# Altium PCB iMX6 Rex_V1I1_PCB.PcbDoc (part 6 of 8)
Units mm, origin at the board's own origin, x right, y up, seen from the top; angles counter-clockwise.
Board outline 70 x 40 mm, 12 copper layers (L1, L2, L3, L4, L5 (PWR), L6 (PWR), L7 (PWR), L8 (PWR), L9, L10, L11, L12), stack 1.566 mm thick; 473 components, 409 nets, 2294 pads, 1880 vias.
Unrouted connection lines stored in the file: 7.
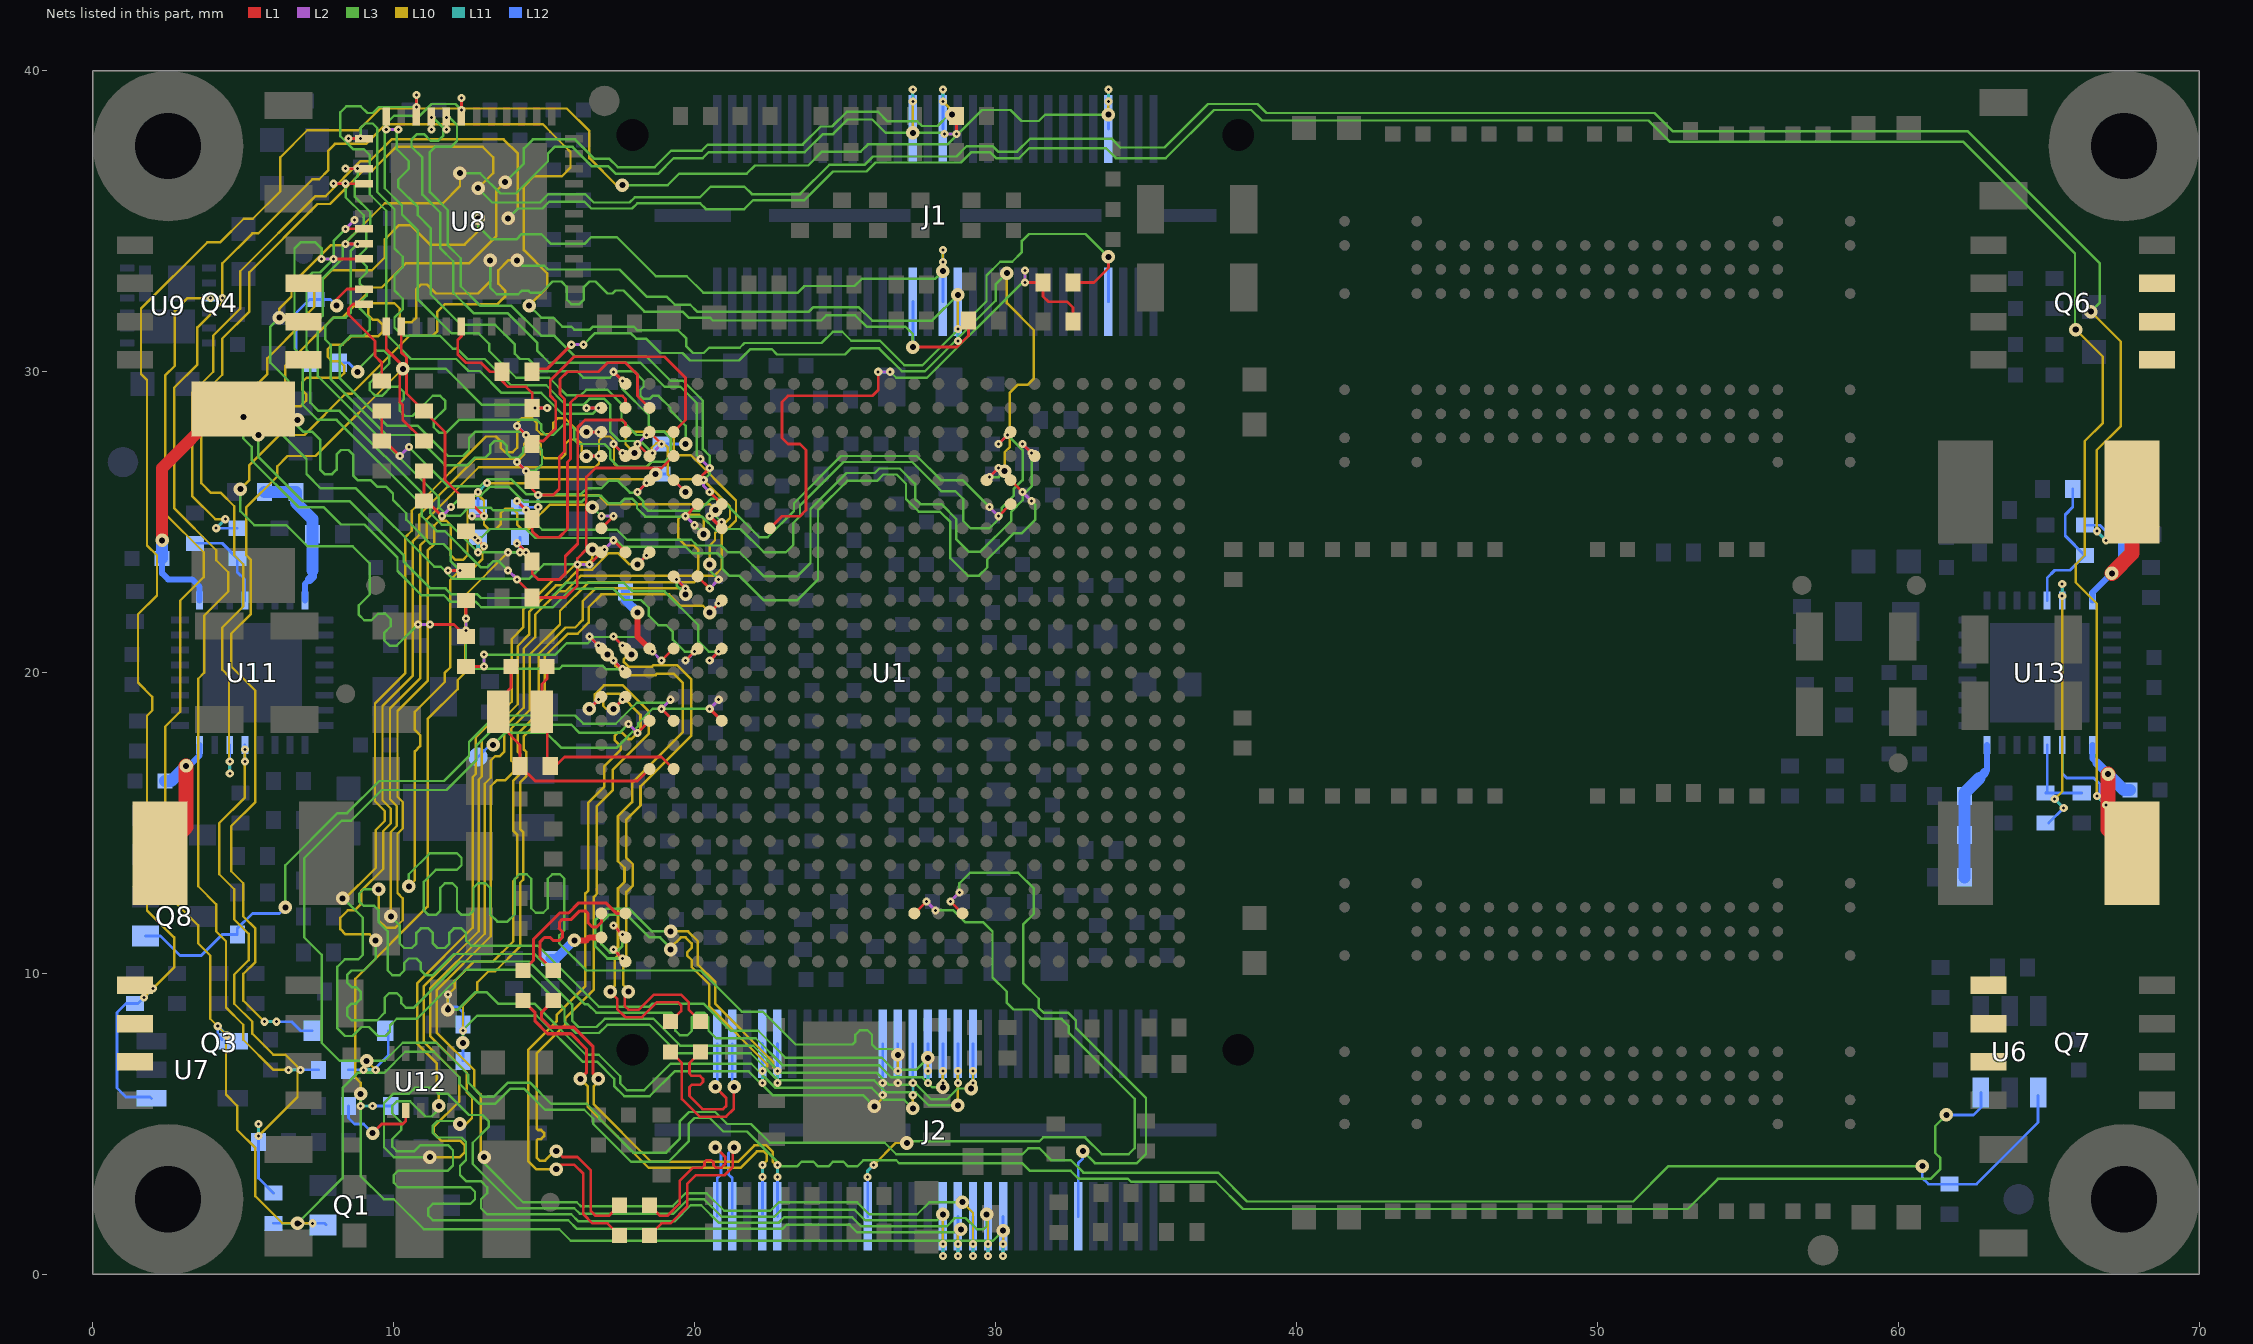
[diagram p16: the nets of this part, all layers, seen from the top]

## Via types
v1: diameter 0.45, hole 0.2, L1 to L12, tented both sides, 761 vias
v2: diameter 0.27, hole 0.1, L1 to L2, 305 vias
v3: diameter 0.27, hole 0.1, L2 to L3, 290 vias
v4: diameter 0.45, hole 0.2, L3 to L10, 196 vias
v5: diameter 0.27, hole 0.1, L11 to L12, 185 vias
v6: diameter 0.27, hole 0.1, L10 to L11, 142 vias
v7: diameter 0.45, hole 0.2, L3 to L10, tented both sides, 1 vias

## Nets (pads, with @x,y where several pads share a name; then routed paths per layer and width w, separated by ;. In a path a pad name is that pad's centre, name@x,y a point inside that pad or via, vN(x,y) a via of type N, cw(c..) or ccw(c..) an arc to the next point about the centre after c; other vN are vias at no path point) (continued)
PCIE_C_TX_N: C63.1 U1.A3 | length 4.9
  L1 w0.101: C63.1@15.3,10.1 14.865,10.535 14.865,11.061 15.004,11.2 15.2,11.2 15.3,11.1 15.5,11.1 15.6,11.2 15.6,11.4 15.5,11.5 15.504,11.504 15.504,11.7 15.604,11.8 15.9,11.8 16.185,12.085 16.365,12.085 16.45,12 16.45,11.7 16.6,11.55 16.75,11.55 16.9,11.7 U1.A3@16.9,12
PCIE_C_TX_P: C65.1 U1.B3 | length 4.9
  L1 w0.101: C65.1@14.3,10.1 14.65,10.45 14.65,11.15 15.515,12.015 15.811,12.015 16.146,12.35 17.045,12.35 17.396,12 U1.B3@17.7,12
PCIE_REXT: R15.2 U1.A2 | length 2
  L1 w0.2: v1(16,11.1) 16.4,11.1 16.5,11.2 U1.A2@16.9,11.2
  L12 w0.3: R15.2@15.2,10.5 15.4,10.5 v1(16,11.1)
PCIE_RX_N: J2.52 U1.B1 | length 14.1
  L1 w0.101: v2(17.3,10.8) U1.B1@17.7,10.4
  L2 w0.1: v2(17.3,10.8) v3(17.6,10.5)
  L3 w0.085: v3(17.6,10.5) 17.1,10.5 16.7,10.9 16.7,11.783 17.067,12.15 17.833,12.15 18.583,11.4 v4(19.2,11.4)
  L10 w0.085: v4(19.2,11.4) 19.783,11.4 20.103,11.08 20.103,10.3 20.688,9.715 20.688,8.993 22.612,7.068 22.612,6.895 v6(22.75,6.758)
  L11 w0.1: v5(22.75,6.358) v6(22.75,6.758)
  L12 w0.101: v5(22.75,6.358) J2.52@22.75,7.67
PCIE_RX_P: J2.54 U1.B2 | length 14.1
  L1 w0.101: v2(17.3,11.6) U1.B2@17.7,11.2
  L2 w0.1: v2(17.3,11.6) v3(17.6,11.3)
  L3 w0.085: v3(17.6,11.3) 17.6,10.914 17.386,10.7 17.183,10.7 16.9,10.983 16.9,11.7 17.15,11.95 17.75,11.95 18.5,11.2 18.85,11.2 19.2,10.85 v4(19.2,10.8)
  L10 w0.085: v4(19.2,10.8) 19.2,10.859 19.541,11.2 19.7,11.2 19.9,11 19.9,10.853 19.75,10.703 19.75,10.6 19.903,10.447 19.903,10.217 20.488,9.632 20.488,8.91 22.412,6.985 22.412,6.92 v6(22.25,6.758)
  L11 w0.1: v5@22.25,6.358 v6(22.25,6.758)
  L12 w0.101: v5@22.25,6.358 J2.54@22.25,7.67
  other v5: 22.25,6.358
PCIE_TX_N: C63.2 J2.51 | length 14.2
  L1 w0.101: C63.2@15.3,9.1 14.915,8.715 14.915,8.5 15.2,8.215 15.985,8.215 16.615,7.585 16.615,6.685 v1(16.8,6.5)
  L10 w0.085: v1(16.8,6.5) 16.8,6.4 16.641,6.241 16.641,5.659 18.557,3.743 21.438,3.743 21.984,4.289 22.381,4.289 22.6,4.07 22.6,3.743 22.7,3.643 v6(22.75,3.643)
  L11 w0.1: v5(22.75,3.243) v6(22.75,3.643)
  L12 w0.101: J2.51@22.75,1.93 v5(22.75,3.243)
PCIE_TX_P: C65.2 J2.53 | length 14.2
  L1 w0.101: C65.2@14.3,9.1 14.7,8.7 14.7,8.411 15.111,8 15.896,8 16.4,7.496 16.4,6.7 v1(16.2,6.5)
  L10 w0.085: v1(16.2,6.5) 16.441,6.259 16.441,5.576 18.475,3.542 21.52,3.542 22.066,4.089 22.299,4.089 22.4,3.987 22.4,3.793 v6(22.25,3.643)
  L11 w0.1: v5(22.25,3.243) v6(22.25,3.643)
  L12 w0.101: J2.53@22.25,1.93 v5(22.25,3.243)
PCIE_WAKE: J2.39 U1.P3 | length 24.3
  L1 w0.093: U1.P3@27.3,12 v2(27.7,12.4)
  L2 w0.1: v2(27.7,12.4) v3(28,12.1)
  L3 w0.08: v4(27.05,4.368) 27.107,4.425 31.455,4.425 31.585,4.555 32.975,4.555 33.53,4 34.425,4 34.625,4.2 34.625,5.835 32.438,8.023 32.438,8.251 32.196,8.493 31.522,8.493 31.209,8.805 30.595,8.805 30.375,9.025 30.375,9.395 29.9,9.87 29.9,11.4 29.6,11.7 29,11.7 28.6,12.1 v3(28,12.1)
  L10 w0.08: v6(25.95,3.643) 26.676,4.368 v4(27.05,4.368)
  L11 w0.1: v5(25.75,3.243) 25.75,3.443 v6(25.95,3.643)
  L12 w0.093: J2.39@25.75,1.93 v5(25.75,3.243)
PHASE1_2V5: C230.1 L4.2 Q6.5 Q6.6 Q6.7 U13.16 | length 6.7
  L1 w0.5: v1(67.1,23.3) 67.769,23.969 L4.2@67.769,26
  L12 w0.2: U13.16@66.45,22.4 66.45,22.65 v1(67.1,23.3) ; 67.4,23.6 67.4,24.5 C230.1@67.5,24.6
  L12 w0.4: v1(67.1,23.3) 67.4,23.6 67.5,23.7 C230.1@67.5,24.6
PHASE1_3V3: C211.1 L1.2 Q3.5 Q3.6 Q3.7 U11.16 | length 5.1
  L1 w0.5: L1.2@2.231,14 3.1,14.869 v1(3.1,16.9)
  L12 w0.2: v1(3.1,16.9) 3.2,16.9 3.55,17.25 U11.16@3.55,17.6
  L12 w0.4: C211.1@2.4,16.4 2.6,16.4 v1(3.1,16.9)
PHASE2_1V5: C231.2 L5.1 Q7.5 Q7.6 Q7.7 U13.25 | length 5.1
  L1 w0.5: v1(66.975,16.625) 66.975,14.794 L5.1@67.769,14
  L12 w0.2: U13.25@66.45,17.6 66.45,17.15 66.6,17
  L12 w0.3: 66.6,17 v1(66.975,16.625)
  L12 w0.4: v1(66.975,16.625) 67.5,16.1 C231.2@67.7,16.1
PHASE2_1V375: C212.2 L2.1 Q4.5 Q4.6 Q4.7 U11.25 | length 8.9
  L1 w0.4: v1(2.3,24.4) 2.3,26.8 4.269,28.769 L2.1@5,28.769
  L12 w0.2: C212.2@2.3,23.8 2.3,23.3 2.5,23.1 3.3,23.1 3.55,22.85 U11.25@3.55,22.4
  L12 w0.4: C212.2@2.3,23.8 v1(2.3,24.4)
PMIC_ON_REQ: Q8.1 R73.1 U1.D11 | length 23.7
  L1 w0.093: v2(18.9,18.8) U1.D11@19.3,18.4
  L2 w0.1: v2(18.9,18.8) v3(19.2,19.1)
  L3 w0.08: v1(6.4,12.2) 6.4,13.6 8.13,15.33 8.447,15.33 9.517,16.4 11.666,16.4 12.5,17.234 12.5,17.7 13.375,18.575 16.025,18.575 16.3,18.3 17.375,18.3 18.075,19 19.1,19 v3(19.2,19.1)
  L12 w0.093: Q8.1@1.75,11.25 2.25,11.25 2.9,10.6 3.6,10.6 4.3,11.3 R73.1@4.8,11.3 4.8,11.5 5.3,12 6.2,12 v1(6.4,12.2)
PMIC_STBY_REQ: TP3.1 U1.F11 | length 10.2
  L1 w0.093: v2(20.5,18.8) U1.F11@20.9,18.4
  L2 w0.1: v2(20.5,18.8) v3(20.8,19.1)
  L3 w0.08: v1(13.3,17.6) 13.7,18 15.07,18 15.57,17.5 17.403,17.5 18.125,18.222 18.125,18.321 18.604,18.8 v2(20.5,18.8) v3(20.8,19.1)
  L12 w0.093: TP3.1@12.8,17.2 13.2,17.6 v1(13.3,17.6)
POK_1V5: R164.1 U13.14 | length 8.9
  L10 w0.08: v6(65.2,15.8) 65.45,16.05 v6(65.45,22.55)
  L11 w0.1: v6(65.2,15.8) v5(65.5,15.5) ; v6(65.45,22.55) v5(65.45,22.95)
  L12 w0.093: R164.1@65,15 v5(65.5,15.5) ; U13.14@65.45,22.4 v5(65.45,22.95)
POK_1V5_R: R154.1 R164.2 U13.28 | length 2.8
  L12 w0.093: U13.28@64.95,17.6 64.95,16.05 R164.2@64.9,16 R154.1@66.1,16
POK_1V375: R108.1 U13.27 | length 103.1
  L3 w0.08: v4(13.8,35.1) 14.125,35.425 14.938,35.425 15.163,35.65 16.337,35.65 16.562,35.425 17.921,35.425 18.096,35.6 20.18,35.6 20.375,35.405 21.649,35.405 21.949,35.705 23.645,35.705 24.595,36.655 25.707,36.655 26.007,36.955 28.855,36.955 29.2,37.3 29.817,37.3 30.017,37.1 30.786,37.1 31.116,37.43 33.67,37.43 34,37.1 35.655,37.1 37.255,38.7 38.5,38.7 38.85,38.35 51.7,38.35 52.4,37.65 62.15,37.65 65.875,33.925 65.875,31.425 v4(65.9,31.4)
  L10 w0.08: v6(4.4,25.1) 4.07,25.1 3.3,25.87 3.3,29.3 4,30 4,31.2 4.9,32.1 4.9,33.338 7.4,35.838 7.738,35.838 8.9,37 9.2,37 9.925,37.725 13.65,37.725 14.125,37.25 14.125,35.425 v4(13.8,35.1) ; v4(65.9,31.4) 66.8,30.5 66.8,28.3 66.2,27.7 66.2,23.9 65.9,23.6 65.9,23 66.6,22.3 v6(66.6,15.9)
  L11 w0.1: v5(4.1,24.8) v6(4.4,25.1) ; v6(66.6,15.9) v5(66.9,15.6)
  L12 w0.093: v5@4.2,24.8 R108.1@4.8,24.8 ; U13.27@65.45,17.6 65.45,16.65 65.6,16.5 66.5,16.5 66.7,16.3 66.7,15.8 v5(66.9,15.6)
POK_1V375_R: R108.2 R130.1 U11.28 | length 3.1
  L12 w0.093: R130.1@3.4,24.3 4.3,24.3 R108.2@4.8,23.8 4.8,23.35 5.05,23.1 U11.28@5.05,22.4
POK_2V5: R163.1 U11.14 | length 100.4
  L3 w0.08: v4(12.8,36.1) 13.275,35.625 14.855,35.625 15.13,35.9 16.37,35.9 16.645,35.625 17.838,35.625 18.013,35.8 20.177,35.8 20.532,36.155 21.65,36.155 21.9,35.905 23.505,35.905 24.475,36.875 25.644,36.875 25.924,37.155 28.7,37.155 29.045,37.5 29.9,37.5 30.085,37.315 30.718,37.315 31.153,37.75 33.85,37.75 34.145,37.455 35.61,37.455 37.055,38.9 38.7,38.9 39,38.6 51.9,38.6 52.5,38 62.3,38 66.7,33.6 66.7,32.3 v4(66.4,32)
  L10 w0.08: v6(4.55,17.05) 4.525,17.075 4.525,19.875 4.3,20.1 4.3,21.5 5,22.2 5,23.601 4.7,23.901 4.7,25.53 4.255,25.975 3.925,25.975 3.6,26.3 3.6,29.2 4.3,29.9 4.3,31.1 5.2,32 5.2,33.305 7.47,35.575 7.875,35.575 9,36.7 9.3,36.7 10.075,37.475 12.955,37.475 13.3,37.13 13.3,36.6 v4(12.8,36.1) ; v4(66.4,32) 67.4,31 67.4,28.2 66.6,27.4 v6(66.6,24.7)
  L11 w0.1: v5(4.55,16.65) v6(4.55,17.05) ; v6(66.6,24.7) v5(66.9,24.4)
  L12 w0.093: v5(4.55,16.65) U11.14@4.55,17.6 ; R163.1@66.2,24.9 66.7,24.9 66.9,24.7 v5(66.9,24.4)
POK_2V5_R: R153.1 R163.2 U13.13 | length 4.9
  L12 w0.093: U13.13@64.95,22.4 64.95,23.15 65.203,23.403 65.703,23.403 R163.2@66.2,23.9 65.55,24.55 65.55,25.25 65.8,25.5 R153.1@65.8,26.1
POK_3V0_SNVS: R93.1 U12.7 | length 3
  L1 w0.093: v1(9.3,4.7) 9.6,5 10.3,5 10.4,5.1 U12.7@10.4,5.45
  L12 w0.093: R93.1@8.5,5.6 8.5,5.2 8.7,5 9,5 v1(9.3,4.7)
POK_3V3: Q1.1 R107.1 U6.3 U7.4 U9.9 | length 107.3
  L3 w0.08: v4(6.8,1.7) 8.3,3.2 8.3,6.2 8.8,6.7 9.683,6.7 10.383,7.4 11.33,7.4 12.175,6.555 12.175,6.345 12.85,5.67 13.37,5.67 13.875,6.175 14.325,6.175 15.025,5.475 16.33,5.475 16.63,5.175 16.63,5 17.885,3.745 19.128,3.745 19.8,4.417 19.8,5 20,5.2 20.5,5.2 20.95,4.75 21.744,4.75 22.901,3.593 23.405,3.593 23.555,3.743 23.945,3.743 24.095,3.593 24.445,3.593 24.595,3.743 24.945,3.743 25.095,3.593 25.405,3.593 25.606,3.794 ; 25.607,3.793 26.7,3.793 26.8,3.693 30.894,3.693 31.145,3.443 32.5,3.443 32.76,3.183 34.4,3.183 34.5,3.083 37.317,3.083 38.225,2.175 53.005,2.175 54.005,3.175 54.2,3.175 61.075,3.175 61.4,3.5 61.4,3.87 61.225,4.045 61.225,4.925 v1(61.6,5.3)
  L10 w0.08: v6(3.91,32.45) 3.15,32.45 2.725,32.025 2.725,30.2 2.4,29.875 2.4,25.283 3.683,24 3.683,23.174 2.9,22.391 2.9,18.7 2.4,18.2 2.4,12.7 3.5,11.6 3.5,11 3.9,10.6 3.9,8.5 v6(4.45,7.95) 4.425,7.925 4.425,5.975 4.8,5.6 4.8,4.8 5.4,4.2 5.4,2.6 6.3,1.7 v4(6.8,1.7) v6(7.3,1.7)
  L11 w0.1: v6(3.91,32.45) v5(4.31,32.45) ; v5(4.15,8.25) v6(4.45,7.95) ; v5(6.9,1.7) v6(7.3,1.7)
  L12 w0.093: U9.9@3.86,32.45 v5(4.31,32.45) ; v5(4.15,8.25) 4.15,7.95 U7.4@4.3,7.8 ; R107.1@6,1.7 7.7,1.7 Q1.1@7.75,1.65 ; v1(61.6,5.3) 62.5,5.3 62.75,5.55 U6.3@62.75,6.05
POK_3V3_R: R107.2 R129.1 U11.13 | length 19.3
  L10 w0.08: v6(5.05,17.45) 5.05,15.85 4.2,15 4.2,13.3 4.7,12.8 4.7,11.8 5.175,11.325 5.175,10.445 4.7,9.97 4.7,8.997 5.3,8.397 5.3,8 6,7.3 6.403,7.3 6.8,6.903 6.8,5.9 v6(5.5,4.6)
  L11 w0.1: v5(5.05,17.05) v6(5.05,17.45) ; v6(5.5,4.6) v5(5.5,5)
  L12 w0.093: v5(5.05,17.05) U11.13@5.05,17.6 ; v5(5.5,5) R129.1@5.5,4.4 5.5,3.2 R107.2@6,2.7
POR_BN: D1.1 R60.1 R70.1 U1.C11 U6.1 | length 88.3
  L1 w0.093: v2(18.1,18) U1.C11@18.5,18.4
  L2 w0.1: v3(17.8,18.3) v2(18.1,18)
  L3 w0.08: v3(17.8,18.3) 17.5,18 16.175,18 15.9,18.275 13.445,18.275 12.75,17.58 12.75,17.101 11.749,16.1 9.6,16.1 8.58,15.08 8.267,15.08 7.025,13.838 7.025,11.2 7.6,10.625 7.6,7.7 8.2,7.1 v4(9.1,7.1) 9.7,7.1 10.3,7.7 11.413,7.7 12.475,6.638 12.475,6.378 12.953,5.9 13.317,5.9 13.792,6.375 14.525,6.375 15.225,5.675 16.413,5.675 16.83,5.258 16.83,5.183 17.963,4.05 19.05,4.05 19.5,4.5 19.5,5.083 19.817,5.4 20.683,5.4 21.083,5 21.877,5 22.5,4.377 26.316,4.377 26.7,3.993 30.893,3.993 31.093,4.193 31.455,4.193 31.848,3.8 32.5,3.8 32.918,3.383 37.4,3.383 38.358,2.425 51.195,2.425 52.37,3.6 v1(60.8,3.6)
  L10 w0.08: v4(9.1,7.1) v6(9.4,6.8)
  L11 w0.1: v5(9,6.8) v6(9.4,6.8)
  L12 w0.093: R70.1@8.5,6.8 v5(9,6.8) 9.325,6.8 9.819,7.294 D1.1@9.819,8.1 ; v1(60.8,3.6) 60.8,3.4 60.8,3.2 61,3 61.2,3 R60.1@61.7,3 62.6,3 64.65,5.05 U6.1@64.65,5.95
REFIN2_1V5: R134.1 R135.1 R158.2 U13.32 | length 4.7
  L12 w0.2: 62.875,16.675 62.95,16.75 U13.32@62.95,17.6
  L12 w0.3: 62.7,16.5 62.875,16.675
  L12 w0.4: R158.2@62.2,13.2 R134.1@62.2,14.6 R135.1@62.2,15.9 62.2,16 62.7,16.5
REFIN2_1V375: R119.1 R120.2 R136.2 U11.32 | length 5.5
  L12 w0.2: U11.32@7.05,22.4 7.05,22.95 7.2,23.1 ; R120.2@7.3,24.6 7.3,25.1
  L12 w0.3: 7.2,23.1 7.3,23.2 7.3,23.4
  L12 w0.4: R136.2@5.7,26 R119.1@6.75,26 6.75,25.65 7.3,25.1 R120.2@7.3,24.6 7.3,23.4
RGMII_INT: R88.2 R89.1 U1.W22 U8.38 | length 35
  L1 w0.093: U8.38@10.25,31.51 10.25,30.65 10.425,30.475 10.425,29.275 R89.1@11,28.7 11.7,28 11.7,26.4 R88.2@12.4,25.7 12.5,25.7 v2(13,25.2) ; v2(30.9,27.6) U1.W22@31.3,27.2
  L2 w0.1: v3(12.6,25.2) v2(13,25.2) ; v2(30.9,27.6) v3(31.2,27.3)
  L3 w0.08: v3(12.6,25.2) 12.7,25.1 14.583,25.1 14.933,24.75 17.42,24.75 17.755,24.415 19.885,24.415 20.075,24.225 20.875,24.225 21.1,24 21.5,24 22.3,23.2 23.4,23.2 23.85,23.65 23.85,25.436 25.05,26.636 25.986,26.636 26.135,26.785 26.815,26.785 27.325,26.275 27.325,25.775 27.5,25.6 28.2,25.6 28.7,25.1 28.7,24.425 29.1,24.025 29.5,24.025 30.525,25.05 30.525,25.355 30.9,25.73 30.9,25.892 31.2,26.193 v3(31.2,27.3)
RGMII_INT_R: R88.1 U1.V21 | length 29.2
  L1 w0.093: R88.1@12.4,24.7 12.5,24.7 v2(13,24.2) ; U1.V21@30.5,26.4 v2(30.9,26)
  L2 w0.1: v3(12.7,24.5) v2(13,24.2) ; v2(30.9,26) v3(31.2,25.7)
  L3 w0.08: v3(12.7,24.5) 12.925,24.5 13.2,24.775 14.4,24.775 14.7,24.475 17.325,24.475 17.615,24.185 19.7,24.185 19.91,23.975 20.755,23.975 20.925,23.805 20.925,23.445 21.145,23.225 21.475,23.225 22.3,22.4 23.4,22.4 24.1,23.1 24.1,25.403 25.072,26.375 26.058,26.375 26.268,26.585 26.718,26.585 27.025,26.278 27.025,25.775 27.45,25.35 28.153,25.35 28.5,25.003 28.5,23.8 29.075,23.225 29.455,23.225 29.725,23.495 29.725,23.755 30.6,24.63 30.861,24.63 31.325,25.095 31.325,25.575 v3(31.2,25.7)
RGMII_MDC: R85.1 R87.1 U1.V20 | length 26.8
  L1 w0.093: R85.1@9.6,28.8 R85.1@9.6,28.7 R87.1@9.6,27.7 9.7,27.7 v2(10.2,27.2) ; v2(30.1,25.2) U1.V20@30.5,25.6
  L2 w0.1: v2(10.2,27.2) v3(10.5,27.5) ; v3(29.8,25.5) v2(30.1,25.2)
  L3 w0.08: v3(10.5,27.5) 11.8,26.2 12.875,26.2 13.1,26.425 13.908,26.425 14.398,25.935 16.222,25.935 16.412,26.125 16.895,26.125 17.145,26.375 17.455,26.375 17.845,25.985 18.001,25.985 18.285,25.701 18.285,25.545 18.445,25.385 20.155,25.385 20.545,25.775 20.875,25.775 22.15,24.5 22.425,24.5 23.3,25.375 23.3,25.633 24.867,27.2 27.383,27.2 28.183,26.4 28.9,26.4 v3(29.8,25.5)
RGMII_MDIO: R86.1 R162.1 U1.V23 | length 29.7
  L1 w0.093: R86.1@11,26.7 11,25.8 v2(11.6,25.2) ; v2(30.1,27.6) U1.V23@30.5,28
  L2 w0.1: v2(11.6,25.2) v3(11.9,25.5) ; v2(30.1,27.6) v3(30.4,27.9)
  L3 w0.08: v3(11.9,25.5) 12.3,25.9 12.908,25.9 13.183,26.175 13.825,26.175 14.315,25.685 16.255,25.685 16.445,25.875 16.895,25.875 17.145,25.625 17.522,25.625 17.682,25.785 17.918,25.785 18.085,25.618 18.085,25.463 18.362,25.185 20.245,25.185 20.715,24.715 21.018,24.715 21.078,24.775 21.525,24.775 22.3,24 23.03,24 23.275,24.245 23.275,24.975 23.5,25.2 23.5,25.55 24.95,27 27.23,27 28.2,26.03 28.67,26.03 28.925,25.775 28.925,25.045 29.17,24.8 29.8,24.8 30.2,25.2 30.2,25.475 30.6,25.875 30.6,26.1 30.9,26.4 30.9,27.4 v3(30.4,27.9)
RGMII_R_MDC: R85.2 U8.36 | length 3.4
  L1 w0.093: U8.36@9.01,32.25 8.65,32.25 8.5,32.1 8.5,31.9 9.375,31.025 9.375,30.525 9.6,30.3 R85.2@9.6,29.7
RGMII_R_MDIO: R86.2 U8.37 | length 4.3
  L1 w0.093: U8.37@9.75,31.51 9.75,30.75 10.2,30.3 10.2,29 10.3,28.9 10.3,28.4 R86.2@11,27.7
RGMII_R_RXCLK: R83.2 R101.2 U8.35 | length 4.8
  L1 w0.093: v1(8.1,32.2) 8.1,32.4 8.45,32.75 U8.35@9.01,32.75
  L12 w0.093: R83.2@7.2,30.3 7.1,30.3 6.75,30.65 6.75,31.95 7.2,32.4 R101.2@7.4,32.4 7.9,32.4 v1(8.1,32.2)
RGMII_R_TXCLK: R35.1 U1.D21 | length 1.6
  L1 w0.093: U1.D21@19.3,26.4 v1(19.7,26)
  L12 w0.093: R35.1@18.9,26.6 19.1,26.6 v1(19.7,26)
RGMII_RSTN: D1.2 R65.2 R75.1 U8.42 | length 38.3
  L1 w0.093: U8.42@12.25,31.51 12.25,31.18 12.125,31.055 12.125,30.575 12.4,30.3 12.9,30.3 13.2,30 R65.2@13.6,30 13.6,29.7 13.8,29.5 14.4,29.5 14.6,29.3 R75.1@14.6,28.9 ; R75.1@14.6,28.8 v2(15.1,28.8)
  L2 w0.1: v3(14.7,28.8) v2(15.1,28.8)
  L3 w0.08: v4(10.3,30.1) 11.73,30.1 12.93,28.9 14.6,28.9 v3(14.7,28.8)
  L10 w0.08: v6(5.7,8.4) 5,9.1 5,9.987 5.4,10.387 5.4,11.5 5,11.9 5,13 4.6,13.4 4.6,14.9 5.4,15.7 5.4,19.4 4.6,20.2 4.6,21.3 5.25,21.95 5.25,23.75 5.1,23.9 5.1,25.5 6.125,26.525 6.125,26.855 6.47,27.2 7.4,27.2 v4(10.3,30.1)
  L11 w0.1: v6(5.7,8.4) v5(6.1,8.4)
  L12 w0.093: v5(6.1,8.4) 6.6,8.4 6.9,8.1 D1.2@7.281,8.1
RGMII_RSTN_R: R65.1 U1.U21 | length 28.1
  L1 w0.093: R65.1@14.6,30.1 15.1,30.1 15.5,30.5 v2(15.9,30.9) ; U1.U21@29.7,26.4 v2(30.1,26.8)
  L2 w0.1: v2(15.9,30.9) v3(16.3,30.9) ; v3(29.8,26.5) v2(30.1,26.8)
  L3 w0.08: v3(16.3,30.9) 16.675,31.275 17.884,31.275 18.059,31.1 18.387,31.1 18.862,30.625 19.6,30.625 19.85,30.375 21.475,30.375 21.855,30.755 22.56,30.755 22.74,30.575 25,30.575 25.2,30.775 26.128,30.775 26.886,30.018 27.655,30.018 30,32.363 30,32.905 v4(30.375,33.28) ; v3(29.8,26.5) 30.1,26.5 v4(30.3,26.7)
  L10 w0.08: v4(30.3,26.7) 30.3,27.325 30.475,27.5 30.475,29.305 30.745,29.575 31.075,29.575 31.275,29.775 31.275,31.38 30.375,32.28 v4(30.375,33.28)
RGMII_RXCLK: R83.1 U1.B25 | length 22.7
  L1 w0.093: v2(17.3,30) U1.B25@17.7,29.6
  L2 w0.1: v2(17.3,30) v3(17.6,29.7)
  L3 w0.08: v1(8.8,30) 8.8,30.07 9.43,30.7 9.674,30.7 9.85,30.523 9.85,30.28 9.2,29.63 9.2,29.386 9.377,29.21 9.62,29.21 9.91,29.5 10.154,29.5 10.33,29.323 10.33,29.08 10.2,28.95 10.2,28.706 10.377,28.53 10.62,28.53 11.295,29.205 11.538,29.205 11.715,29.028 11.715,28.785 11.33,28.4 11.33,28.157 11.507,27.98 11.75,27.98 12.17,28.4 14.75,28.4 14.9,28.25 14.9,28.05 15.05,27.9 15.3,27.9 15.65,28.25 15.85,28.25 16,28.1 16,27.735 16.135,27.6 17,27.6 17.2,27.4 17.2,27.1 17.45,26.85 18.42,26.85 18.585,27.015 19.015,27.015 19.2,27.2 19.2,27.8 19,28 18.703,28 18.475,28.228 18.475,28.555 17.6,29.43 v3(17.6,29.7)
  L12 w0.093: R83.1@8.2,30.3 8.5,30.3 v1(8.8,30)
RGMII_RXD0: R98.1 U1.C24 U8.32 | length 27.4
  L1 w0.093: v2(8.4,34.25) U8.32@9.01,34.25 ; v2(14.1,27) 14.6,26.5 14.6,26.1 14.8,25.9 15.3,25.9 15.5,26.1 15.5,27.17 15.675,27.345 15.675,29.1 15.525,29.25 15.525,29.755 15.77,30 16.8,30 17.1,30.3 17.7,30.3 18.1,29.9 18.1,29.2 U1.C24@18.5,28.8
  L2 w0.1: v2(8.4,34.25) v3(8.8,34.25) ; v2(14.1,27) v3(14.4,26.7)
  L3 w0.08: v3(8.8,34.25) 8.575,34.025 8.575,31.975 8.4,31.8 8,31.8 7.725,31.525 7.725,31.075 7.9,30.9 7.9,29.763 9.763,27.9 10.7,27.9 11.7,26.9 12.45,26.9 12.7,27.15 13.05,27.15 13.2,27.3 13.2,27.55 13.35,27.7 13.6,27.7 13.75,27.55 13.75,27.3 13.9,27.15 14.15,27.15 14.3,27.3 14.3,27.45 14.45,27.6 14.725,27.6 14.925,27.4 14.925,26.925 14.715,26.715 14.415,26.715 v3(14.4,26.7)
RGMII_RXD1: R97.1 U1.B23 U8.31 | length 27.4
  L1 w0.093: v2(8.4,34.75) U8.31@9.01,34.75 ; v2(14.1,24.3) 14.6,23.8 R97.1@14.6,23.7 14.6,23.3 14.8,23.1 15.5,23.1 15.7,23.3 15.7,23.87 16.115,24.285 16.115,28.157 16.358,28.4 17.6,28.4 17.7,28.3 U1.B23@17.7,28
  L2 w0.1: v2(8.4,34.75) v3(8.7,35.05) ; v2(14.1,24.3) v3(14.4,24)
  L3 w0.08: v3(8.7,35.05) 8,34.35 8,33.747 7.553,33.3 7.3,33.3 7.1,33.1 7.1,30.721 7.225,30.596 7.225,28.975 7.5,28.7 8.2,28.7 11.217,25.683 11.217,25.3 11.6,24.917 11.88,24.917 12.797,24 v3(14.4,24)
RGMII_RXD2: R96.1 U1.B24 U8.28 | length 27.4
  L1 w0.093: v2(8,36.25) U8.28@9.01,36.25 ; v2(14.1,25.7) 14.6,25.2 R96.1@14.6,25.1 14.6,24.7 14.8,24.5 15.5,24.5 15.775,24.775 15.775,27 15.875,27.1 15.875,28.975 16.1,29.2 17.6,29.2 17.7,29.1 U1.B24@17.7,28.8
  L2 w0.1: v2(8,36.25) v3(8.4,36.25) ; v2(14.1,25.7) v3(14.4,25.4)
  L3 w0.08: v3(8.4,36.25) 8.4,35.8 9,35.2 9,34.9 8.3,34.2 8.3,33.764 7.636,33.1 7.636,31.861 7.475,31.7 7.475,29.855 11.5,25.83 11.5,25.497 11.782,25.215 12.212,25.215 12.482,25.485 13.215,25.485 13.3,25.4 v3(14.4,25.4)
RGMII_RXD3: R95.1 U1.D23 U8.27 | length 28.3
  L1 w0.093: v2(8.4,36.75) U8.27@9.01,36.75 ; v2(14.1,28.2) 14.6,27.7 R95.1@14.6,27.6 R95.1@14.65,27.65 ; R95.1@14.7,27.6 R95.1@14.65,27.65 ; U1.D23@19.3,28 19.7,28.4 19.7,29.8 19,30.5 15.987,30.5 15.2,29.713 15.2,29.203 15.385,29.018 15.385,28.115 14.97,27.7 14.7,27.7 R95.1@14.65,27.65
  L2 w0.1: v2(8.4,36.75) v3(8.8,36.75) ; v2(14.1,28.2) v3(14.4,27.9)
  L3 w0.08: v3(8.8,36.75) 8.8,36.5 8.7,36.4 8.7,35.825 9.225,35.3 9.225,34.8 9.085,34.66 9.085,34.1 8.875,33.89 8.875,33.725 9.1,33.5 9.1,33.3 8.875,33.075 8.875,32.925 9.1,32.7 9.1,32.525 8.875,32.3 8.875,32.1 9.2,31.775 9.2,31.4 9,31.2 8.575,31.2 8.2,30.825 8.2,29.796 9.796,28.2 10.8,28.2 11.8,27.2 12.3,27.2 12.5,27.4 12.5,27.8 12.7,28 14.3,28
RGMII_RXDV: R91.1 U1.D22 U8.33 | length 27.4
  L1 w0.093: v2(8,33.75) U8.33@9.01,33.75 ; v2(14.1,23.1) 14.7,22.5 15.7,22.5 16.1,22.9 16.1,23.8 16.4,24.1 16.4,26.5 16.7,26.8 18.9,26.8 U1.D22@19.3,27.2
  L2 w0.1: v3(7.6,33.75) v2(8,33.75) ; v3(13.8,23.4) v2(14.1,23.1)
  L3 w0.08: v3(7.6,33.75) 7.6,34.1 7.4,34.3 6.9,34.3 6.7,34.1 6.7,30.763 6.975,30.488 6.975,28.9 7.475,28.4 8.1,28.4 10.934,25.566 10.934,25.2 11.434,24.7 11.7,24.7 12.9,23.5 13.1,23.5 13.3,23.7 13.5,23.7 v3(13.8,23.4)
RGMII_TXCLK: R35.2 U8.24 | length 19.7
  L1 w0.093: v2(9.75,38.05) U8.24@9.75,38.49
  L2 w0.1: v2(9.75,38.05) v3(10.15,38.05)
  L3 w0.08: v3(10.15,38.05) 10.1,38 10.1,37.4 10.5,37 10.5,36.737 10.15,36.387 10.15,36.125 10.8,35.475 10.8,35.2 11.225,34.775 11.225,32.575 12.237,31.562 13.368,31.562 14.025,30.905 14.025,30.6 14.2,30.425 14.475,30.425 14.88,30.02 16.08,30.02 16.3,29.8 17.18,29.8 17.4,30.02 17.98,30.02 18.3,29.7 18.3,29.5 18.2,29.4 18.2,29.2 18.3,29.1 18.5,29.1 18.6,29.2 18.8,29.2 19.197,28.803 19.197,28.711 19.7,28.208 v1(19.7,27.6)
  L12 w0.093: R35.2@18.9,27.6 v1(19.7,27.6)
RGMII_TXD0: U1.C22 U8.19 | length 21.2
  L1 w0.093: U8.19@12.25,38.49 v2(12.25,39.1) ; v2(18.1,27.6) U1.C22@18.5,27.2
  L2 w0.1: v3(12.25,38.7) v2(12.25,39.1) ; v2(18.1,27.6) v3(18.4,27.9)
  L3 w0.08: v3(12.25,38.7) 12.05,38.9 11.253,38.9 10.868,38.515 10.015,38.515 9.7,38.2 9.7,36.1 10.275,35.525 10.275,35.225 10.8,34.7 10.8,32.4 11.925,31.275 12.825,31.275 13.17,30.93 13.17,30.7 14.07,29.8 15.17,29.8 15.745,29.225 16.225,29.225 16.4,29.4 17.1,29.4 17.57,28.93 17.57,28.4 18.07,27.9 v3(18.4,27.9)
RGMII_TXD1: U1.F20 U8.20 | length 21.2
  L1 w0.093: v2(11.75,38.05) U8.20@11.75,38.49 ; v2(20.5,26) U1.F20@20.9,25.6
  L2 w0.1: v2(11.75,38.05) v3(11.75,38.45) ; v3(20.3,26.4) 20.3,26.2 v2(20.5,26)
  L3 w0.08: v3(11.75,38.45) 11.85,38.45 12.1,38.2 12.1,37.675 11.9,37.475 11.375,37.475 11.2,37.3 11.2,35.97 11.8,35.37 11.8,34.2 12.225,33.775 12.225,32.845 12.87,32.2 13.9,32.2 14.9,31.2 15.33,31.2 16.005,30.525 18.375,30.525 19.2,29.7 19.613,29.7 20.275,29.038 20.275,27.428 20.5,27.203 20.5,26.6 v3(20.3,26.4)
RGMII_TXD2: U1.E21 U8.21 | length 21.3
  L1 w0.093: v2(11.25,38.05) U8.21@11.25,38.49 ; U1.E21@20.1,26.4 v2(20.5,26.8)
  L2 w0.1: v2(11.25,38.05) v3(11.25,38.45) ; v3(20.2,27.1) v2(20.5,26.8)
  L3 w0.08: v3(11.25,38.45) 11.3,38.45 11.65,38.1 11.65,37.857 11.473,37.68 11.23,37.68 11.01,37.9 10.767,37.9 10.59,37.723 10.59,37.48 10.95,37.12 10.95,35.887 11.55,35.287 11.55,34.1 11.975,33.675 11.975,32.625 12.65,31.95 13.78,31.95 14.775,30.955 14.775,30.695 15.17,30.3 18.2,30.3 19,29.5 19.53,29.5 20.075,28.955 20.075,27.225 v3(20.2,27.1)
RGMII_TXD3: U1.A24 U8.22 | length 21.2
  L1 w0.093: U8.22@10.75,38.49 v2(10.75,39.2) ; v2(16.4,28.8) U1.A24@16.9,28.8
  L2 w0.1: v3(10.75,38.8) v2(10.75,39.2) ; v2(16.4,28.8) v3(16.8,28.8)
  L3 w0.08: v3(10.75,38.8) 9.5,38.8 9.3,38.6 9.125,38.6 8.9,38.825 8.425,38.825 8.225,38.625 8.225,37.825 8.65,37.4 9,37.4 9.2,37.2 9.2,35.9 9.75,35.35 9.75,31.25 10.575,30.425 12.079,30.425 12.479,30.025 12.858,30.025 13.583,29.3 14.9,29.3 15.6,28.6 16.6,28.6 v3(16.8,28.8)
RGMII_TXEN: U1.C23 U8.25 | length 21.2
  L1 w0.093: v2(8.5,37.75) U8.25@9.01,37.75 ; U1.C23@18.5,28 v2(18.9,27.6)
  L2 w0.1: v2(8.5,37.75) v3(8.9,37.75) ; v3(18.6,27.3) v2(18.9,27.6)
  L3 w0.08: v3(8.9,37.75) 8.9,38.1 9.05,38.25 9.3,38.25 9.45,38.1 9.45,35.975 10.025,35.4 10.025,34.1 10.3,33.825 10.3,33.475 10.025,33.2 10.025,32.7 10.3,32.425 10.3,32.075 10.025,31.8 10.025,31.475 10.3,31.2 11.53,31.2 11.961,30.77 12.1,30.77 12.445,30.425 13.024,30.425 13.899,29.55 15.067,29.55 15.717,28.9 16.3,28.9 16.5,29.1 17,29.1 17.2,28.9 17.2,28 17.5,27.7 18.197,27.7 18.597,27.3 v3(18.6,27.3)
RSTINN: J1.8 R68.1 U7.1 | length 70.8
  L3 w0.08: v4(17.6,36.2) 19.1,36.2 19.48,36.58 21.725,36.58 22,36.855 23.776,36.855 24.236,37.315 25.518,37.315 25.758,37.555 28.405,37.555 29.55,38.7 30.5,38.7 30.865,38.335 31.435,38.335 31.643,38.543 v4(33.75,38.543)
  L10 w0.08: v6(1.7,9.2) 2.7,10.2 2.7,11.2 1.8,12.1 1.8,18.57 1.975,18.745 1.975,19.195 1.5,19.67 1.5,21.939 2.13,22.57 2.13,23.9 1.8,24.23 1.8,29.725 1.6,29.925 1.6,32.1 3.8,34.3 4.23,34.3 5.015,35.085 5.315,35.085 6.225,35.995 6.225,37.125 7.125,38.025 8.825,38.025 9.55,38.75 15.75,38.75 16.5,38 16.5,37.1 17.4,36.2 v4(17.6,36.2) ; v4(33.75,38.543) v6(33.75,38.982)
  L11 w0.1: v6(1.7,9.2) v5(2,9.5) ; v6(33.75,38.982) v5(33.75,39.383)
  L12 w0.093: U7.1@1.95,5.85 1.9,5.9 1.1,5.9 0.8,6.2 0.8,8.7 1.1,9 R68.1@1.4,9 1.5,9 v5(2,9.5) ; J1.8@33.75,38.07 v5(33.75,39.383)
RSTOUTN: J1.7 R51.2 R70.2 | length 79.2
  L1 w0.093: R51.2@32.575,32.97 33.27,32.97 33.75,33.45 v1(33.75,33.82)
  L3 w0.08: v4(14.5,32.2) 14.9,31.8 15.3,31.8 15.6,31.5 15.9,31.5 16,31.4 16.517,31.4 16.617,31.5 17.975,31.5 18.1,31.375 19.455,31.375 19.725,31.105 19.725,30.845 19.945,30.625 20.3,30.625 20.475,30.8 21.5,30.8 21.655,30.955 24.22,30.955 24.595,31.33 24.905,31.33 25.205,31.03 26.156,31.03 26.968,30.218 27.572,30.218 29.7,32.346 29.7,33.2 30.155,33.655 30.555,33.655 30.875,33.975 30.875,34.349 31.107,34.58 32.99,34.58 v1(33.75,33.82)
  L10 w0.08: v6(6.5,6.8) 6,6.8 5,7.8 5,8.3 4.425,8.875 4.425,11.075 4.1,11.4 4.1,12.3 3.5,12.9 3.5,19.8 3.7,20 3.7,21.9 4.5,22.7 4.5,23.335 4.1,23.735 4.1,24.068 2.7,25.468 2.7,29.47 3.475,30.245 3.475,31.475 4.3,32.3 4.3,33.6 5.3,34.6 5.496,34.6 7.296,36.4 7.525,36.4 7.825,36.7 7.825,37.355 8.045,37.575 9.075,37.575 9.725,38.225 14.954,38.225 15.2,37.979 15.7,37.479 15.875,37.304 15.875,36.788 15.587,36.5 14.67,36.5 14.325,36.155 14.325,34.045 15.1,33.27 15.1,32.8 v4(14.5,32.2)
  L11 w0.1: v6(6.5,6.8) v5(6.9,6.8)
  L12 w0.093: v5(6.9,6.8) R70.2@7.5,6.8 ; J1.7@33.75,32.33 v1(33.75,33.82)
RSTOUTN_R: R49.1 R51.1 U1.H19 | length 19.3
  L1 w0.093: U1.H19@22.5,24.8 22.9,25.2 23.496,25.2 23.696,25.4 23.696,27.4 23.496,27.6 23.1,27.6 22.9,27.8 22.9,29 23.1,29.2 25.9,29.2 26.1,29.4 v2(26.1,30) ; v2(30.975,32.97) R51.1@31.575,32.97 31.575,32.505 31.75,32.33 32.375,32.33 32.575,32.13 R49.1@32.575,31.67
  L2 w0.1: v2(26.1,30) v3(26.5,30) ; v2(30.975,32.97) v3(30.975,33.37)
  L3 w0.08: v3(26.5,30) 26.7,29.8 27.72,29.8 30.975,33.055 v3(30.975,33.37)
RTC_XTALI: C85.1 R54.1 U1.D9 Y2.1 | length 7.9
  L1 w0.093: C85.1@15.1,20.2 15.1,19.8 14.925,19.625 Y2.1@14.925,18.7 15.1,18.525 15.1,17 R54.1@15.2,16.9 15.37,16.9 15.67,17.2 18.9,17.2 U1.D9@19.3,16.8
RTC_XTALO: C86.1 R54.2 U1.C9 Y2.2 | length 8.4
  L1 w0.093: C86.1@13.9,20.2 13.9,20 13.9,19.5 13.675,19.275 13.475,19.075 Y2.2@13.475,18.7 13.475,18.325 13.675,18.125 14.2,17.6 R54.2@14.2,16.9 14.7,16.4 18.1,16.4 U1.C9@18.5,16.8
SATA_C_RX_N: C69.1 U1.A14 | length 19.7
  L1 w0.09: v2(16.5,21.2) U1.A14@16.9,20.8 ; v1@17.2,9.392 17.425,9.167 17.425,8.818 17.693,8.55 18.25,8.55 18.75,9.05 19.446,9.05 19.55,8.946 19.55,8.75 C69.1@19.2,8.4
  L2 w0.1: v2(16.5,21.2) v3(16.8,20.9)
  L3 w0.085: v3(16.8,20.9) v4(17.1,20.6)
  L10 w0.085: v4(17.1,20.6) 17.17,20.6 17.37,20.4 17.37,20.234 17.686,19.918 18.698,19.918 18.748,19.968 19.3,19.968 19.6,19.668 19.6,18.016 17.92,16.336 17.92,15.7 17.452,15.233 17.452,13.732 17.668,13.517 17.668,13.048 17.452,12.833 17.452,10.6 17.347,10.495 17.347,9.601 17.2,9.454 v1(17.2,9.4)
SATA_C_RX_P: C70.1 U1.B14 | length 19.7
  L1 w0.09: v2(17.3,21.2) U1.B14@17.7,20.8 ; v1(17.8,9.4) 17.675,9.275 17.675,8.921 17.796,8.8 18.146,8.8 18.646,9.3 19.55,9.3 19.8,9.05 19.8,8.8 C70.1@20.2,8.4
  L2 w0.1: v2(17.3,21.2) v3(17.6,20.9)
  L3 w0.085: v3(17.6,20.9) v4(17.9,20.6)
  L10 w0.085: v1(17.8,9.4) 17.8,9.454 17.627,9.627 17.627,10.379 17.732,10.484 17.732,12.717 17.948,12.932 17.948,13.633 17.732,13.848 17.732,15.117 18.2,15.584 18.2,16.22 19.88,17.9 19.88,19.783 19.416,20.248 18.632,20.248 18.582,20.198 17.802,20.198 17.65,20.35 17.65,20.45 17.8,20.6 v4(17.9,20.6)
SATA_C_TX_N: C71.1 U1.B12 | length 25.7
  L1 w0.09: v1(15.4,3.5) 15.55,3.65 15.996,3.65 16.3,3.346 16.3,2 16.6,1.7 17.1,1.7 C71.1@17.5,1.3 ; v4(17.3,18.8) U1.B12@17.7,19.2
  L2 w0.1: v4(17.3,18.8) v3(17.6,19.1)
  L3 w0.085: v4(17.3,18.8) v3(17.6,19.1)
  L10 w0.085: v1(15.4,3.5) 14.731,3.5 14.468,3.763 14.468,7.463 15.42,8.416 15.42,8.636 16.368,9.583 16.368,12.668 16.468,12.768 16.468,15.683 17,16.216 17,16.896 17.55,17.446 17.55,17.546 17.34,17.756 17.34,17.896 17.45,18.006 17.59,18.006 17.8,17.796 17.9,17.796 18.2,18.096 18.2,18.6 17.5,19.3 17.1,19.3 16.963,19.163 16.963,18.896 17.058,18.8 v4(17.3,18.8)
  other v2: 17.3,18.8
SATA_C_TX_P: C72.1 U1.A12 | length 25.7
  L1 w0.09: v1(15.4,4.1) 15.408,4.1 15.608,3.9 16.1,3.9 16.55,3.45 16.55,2.104 16.704,1.95 17.15,1.95 C72.1@17.5,2.3 ; v2(16.5,18.8) U1.A12@16.9,19.2
  L2 w0.1: v2(16.5,18.8) v3(16.8,19.1)
  L3 w0.085: v2(16.5,18.8) v3(16.8,19.1)
  L10 w0.085: v1(15.4,4.1) 15.346,4.1 15.026,3.78 14.847,3.78 14.748,3.879 14.748,4.448 14.8,4.5 14.9,4.5 15,4.6 15,4.7 14.9,4.8 14.8,4.8 14.748,4.852 14.748,7.348 15.7,8.3 15.7,8.52 16.648,9.467 16.648,12.552 16.748,12.652 16.748,15.567 17.28,16.1 17.28,16.78 18.48,17.98 18.48,18.716 17.616,19.58 16.984,19.58 16.683,19.278 16.683,18.983 v2(16.5,18.8)
  other v4: 16.5,18.8
SATA_REXT: R20.2 U1.C14 | length 2.2
  L1 w0.2: v1(18.1,22) 18.1,21.2 U1.C14@18.5,20.8
  L12 w0.3: R20.2@17.7,22.7 17.7,22.4 v1(18.1,22)
SATA_RX_N: C69.2 J2.58 | length 6
  L1 w0.09: C69.2@19.2,7.4 19.575,7.025 19.575,5.825 20.157,5.243 21.043,5.243 21.3,5.5 21.3,6.22 v1(21.313,6.233)
  L12 w0.09: J2.58@21.25,7.67 21.25,6.295 v1(21.313,6.233)
SATA_RX_P: C70.2 J2.60 | length 6
  L1 w0.09: C70.2@20.2,7.4 19.825,7.025 19.825,6.675 19.9,6.6 20.175,6.6 20.275,6.5 20.275,6.4 20.175,6.3 19.9,6.3 19.825,6.225 19.825,5.929 20.261,5.493 20.939,5.493 21.05,5.604 21.05,5.87 v1(20.688,6.233)
  L12 w0.09: v1(20.688,6.233) 20.75,6.295 20.75,6.4 J2.60@20.75,7.67
SATA_TX_N: C71.2 J2.57 | length 7.2
  L1 w0.09: C71.2@18.5,1.3 18.9,1.7 19.2,1.7 19.75,2.25 19.75,3 20.05,3.3 21,3.3 21.263,3.563 21.263,4.17 v1(21.313,4.22)
  L12 w0.09: J2.57@21.25,1.93 21.25,3.2 21.125,3.325 21.125,4.032 v1(21.313,4.22)
SATA_TX_P: C72.2 J2.59 | length 7.3
  L1 w0.09: C72.2@18.5,2.3 18.85,1.95 19.096,1.95 19.5,2.354 19.5,3.104 19.946,3.55 20.25,3.55 20.325,3.625 20.325,3.725 20.4,3.8 20.55,3.8 20.625,3.725 20.625,3.625 20.7,3.55 20.896,3.55 21.013,3.666 21.013,3.912 v1@20.704,4.22 ; v1(20.688,4.22) v1@20.704,4.22 ; v1@20.7,4.224 v1@20.704,4.22
  L12 w0.09: v1(20.688,4.22) 20.875,4.033 20.875,3.325 20.75,3.2 J2.59@20.75,1.93
SD2_ACT: J2.11 U1.T3 | length 19.9
  L1 w0.093: v2(28.5,12.4) U1.T3@28.9,12
  L2 w0.1: v2(28.5,12.4) v3(28.8,12.7)
  L3 w0.08: v3(28.8,12.7) 28.8,13 29.15,13.35 30.75,13.35 31.275,12.825 31.275,11.988 30.915,11.628 30.915,9.685 31.438,9.162 31.438,8.86 31.605,8.692 32.425,8.692 32.675,8.442 32.675,8.185 35,5.86 35,4 34.7,3.7 33.3,3.7 v1(32.9,4.1)
  L12 w0.093: J2.11@32.75,1.93 32.75,3.7 32.9,3.85 v1(32.9,4.1)
SD2_CD: J2.38 R42.1 U1.F16 | length 42.1
  L1 w0.093: v4(20.5,22) U1.F16@20.9,22.4
  L2 w0.1: v4(20.5,22) v3(20.8,22.3)
  L3 w0.08: v4(12.3,7.7) 12.3,8.13 12.77,8.6 14.75,8.6 16.275,7.075 16.755,7.075 17.325,6.505 17.325,6.262 17.662,5.925 18.508,5.925 19.333,6.75 21.8,6.75 22.6,5.95 25.606,5.95 v4(25.969,5.587) ; v4(20.5,22) v3(20.8,22.3)
  L10 w0.08: v4(12.3,7.7) v6(12.3,8.1) 12.3,8.93 12.775,9.405 12.775,9.705 13.145,10.075 13.375,10.075 14.2,10.9 14.2,13.017 14.3,13.117 14.3,14.7 14.2,14.8 14.2,16.354 14.4,16.554 14.4,17.37 14.325,17.445 14.325,17.896 15.019,18.59 15.019,20.532 15.787,21.3 16.113,21.3 16.475,21.662 16.475,22.175 16.9,22.6 19.158,22.6 19.533,22.225 20.275,22.225 v4(20.5,22) ; v4(25.969,5.587) 26.25,5.867 v6(26.25,5.967)
  L11 w0.1: v4(12.3,7.7) v6(12.3,8.1) ; v6(26.25,5.967) v5@26.25,6.368
  L12 w0.093: R42.1@12.3,7.1 v4(12.3,7.7) ; v5(26.25,6.358) J2.38@26.25,7.67
  other v2: 20.5,22
  other v5: 12.3,7.7
SD2_CLK: J2.36 R66.2 | length 49
  L3 w0.08: v4(10.5,12.9) 10.5,13.3 11.2,14 12.1,14 12.25,13.85 12.25,13.6 12.1,13.45 11.4,13.45 11,13.05 11,12.1 11.15,11.95 11.4,11.95 11.55,12.1 11.55,12.85 11.7,13 11.95,13 12.1,12.85 12.1,12.1 12.25,11.95 12.5,11.95 12.65,12.1 12.65,12.85 12.8,13 13.05,13 13.2,12.85 13.2,11.97 13.445,11.725 13.775,11.725 14.02,11.97 14.02,13.15 14.17,13.3 14.42,13.3 14.57,13.15 14.57,12.17 14.72,12.02 14.97,12.02 15.12,12.17 15.12,13.15 15.27,13.3 15.52,13.3 15.67,13.15 15.67,11.445 15.5,11.275 15.5,11 16.4,10.1 20.2,10.1 21.567,8.733 22.267,8.733 23.357,7.642 25.242,7.642 25.342,7.742 25.342,7.967 25.492,8.117 25.743,8.117 25.892,7.967 25.892,7.642 26.042,7.493 26.555,7.493 v4(26.75,7.298)
  L10 w0.08: v4(10.5,12.9) 10.7,13.1 10.7,17.384 10.875,17.559 10.875,17.925 10.7,18.1 10.7,18.7 11.7,19.7 11.7,20 11.875,20.175 11.875,23.075 12.125,23.325 12.5,23.325 12.95,23.775 12.95,24.25 v6(12.8,24.4) ; v6(26.75,6.758) v4(26.75,7.298)
  L11 w0.1: v5(12.8,24) v6(12.8,24.4) ; v5(26.75,6.358) v6(26.75,6.758)
  L12 w0.093: v5(12.8,24) R66.2@12.8,24.5 ; v5(26.75,6.358) J2.36@26.75,7.67
SD2_CLK_R: R66.1 U1.C21 | length 8.1
  L1 w0.093: v2(18.1,26) U1.C21@18.5,26.4
  L2 w0.1: v2(18.1,26) v3(18.4,26.3)
  L3 w0.08: v3(18.4,26.3) v4(18.7,26.6)
  L10 w0.08: v6(13.1,26.3) 14.575,26.3 14.7,26.425 18.525,26.425 v4(18.7,26.6)
  L11 w0.1: v5(12.8,26) v6(13.1,26.3)
  L12 w0.093: R66.1@12.8,25.5 v5(12.8,26)
SD2_CMD: J2.21 R41.1 R52.2 | length 49.7
  L3 w0.08: v4(8.9,6) 8.9,3.27 9.67,2.5 10,2.5 11,1.5 15.5,1.5 15.882,1.118 29.91,1.118 v4(30.25,1.458)
  L10 w0.08: v6(8.9,5.6) v4(8.9,6) 8.9,6.37 8.725,6.545 8.725,9.825 11.125,12.225 11.125,18.455 12.125,19.455 12.125,19.755 12.375,20.005 12.375,22.575 v6(13.8,24) ; v6(30.25,1.018) v4(30.25,1.458)
  L11 w0.1: v6(8.9,5.6) v5(9.3,5.6) ; v6(13.8,24) v5(14.2,24) ; v5(30.25,0.617) v6(30.25,1.018)
  L12 w0.093: v5(9.3,5.6) R41.1@9.9,5.6 ; v5(14.2,24) R52.2@14.2,24.5 ; v5(30.25,0.617) J2.21@30.25,1.93
SD2_CMD_R: R52.1 U1.F19 | length 8.6
  L1 w0.093: v2(20.5,25.2) U1.F19@20.9,24.8
  L2 w0.1: v2(20.5,25.2) 20.7,25 v3(20.9,25)
  L3 w0.08: v4(20.7,25.4) 20.7,25.2 v3(20.9,25)
  L10 w0.08: v6(14.8,25.9) 16.8,25.9 17.1,25.6 20.5,25.6 v4(20.7,25.4)
  L11 w0.1: v5(14.8,25.5) v6(14.8,25.9)
  L12 w0.093: R52.1@14.2,25.5 v5(14.8,25.5)
SD2_DATA0: J2.26 U1.A22 | length 56.9
  L1 w0.093: v4(16.4,27.2) U1.A22@16.9,27.2
  L2 w0.1: v4(16.4,27.2) v3(16.8,27.2)
  L3 w0.08: v4(9.4,11.1) 9.4,10.5 9,10.1 8.6,10.1 8.45,9.95 8.45,9.7 8.6,9.55 8.75,9.55 8.9,9.4 8.9,9.15 8.75,9 8.6,9 8.45,8.85 8.45,8.6 8.6,8.45 9.45,8.45 9.7,8.7 9.7,9.2 9.85,9.35 10.1,9.35 10.25,9.2 10.25,9.02 10.4,8.87 10.67,8.87 12.2,10.4 14.5,10.4 15.925,8.975 15.925,8.445 16.145,8.225 16.742,8.225 17.017,8.5 18.627,8.5 19.527,7.6 21.949,7.6 22.849,6.7 26.057,6.7 26.457,6.3 27.381,6.3 27.863,5.818 28.38,5.818 28.743,6.18 v4(29.188,6.18) ; v4(16.4,27.2) v3(16.8,27.2)
  L10 w0.08: v4(9.4,11.1) 9.2,11.3 8.4,11.3 8.225,11.475 8.225,11.855 8.47,12.1 8.7,12.1 8.925,12.325 8.925,12.755 9.65,13.48 9.65,14.737 9.9,14.987 9.9,15.483 9.625,15.758 9.625,18.892 10.625,19.892 10.625,24.358 10.85,24.583 10.85,25.25 12.7,27.1 14.184,27.1 14.334,27.25 14.334,27.6 14.484,27.75 14.734,27.75 14.884,27.6 14.884,27.25 15.009,27.125 15.575,27.125 15.7,27.25 15.7,27.6 15.85,27.75 16.1,27.75 16.25,27.6 16.25,27.35 v4(16.4,27.2) ; v4(29.188,6.18) 29.25,6.242 v6(29.25,6.758)
  L11 w0.1: v5(29.25,6.358) v6(29.25,6.758)
  L12 w0.093: v5(29.25,6.358) J2.26@29.25,7.67
  other v2: 16.4,27.2
SD2_DATA1: J2.23 U1.E20 | length 57
  L1 w0.093: v2(19.7,25.2) U1.E20@20.1,25.6
  L2 w0.1: v2(19.7,25.2) v3(20,24.9)
  L3 w0.08: v4(12.2,5) 12.1,5.1 11.45,5.1 11.3,4.95 11.3,4.7 11.45,4.55 12.25,4.55 12.4,4.4 12.4,3.8 12.2,3.6 12.2,3.3 12.4,3.1 12.9,3.1 13.1,2.9 13.1,2.7 12.9,2.5 12.9,2.2 13.1,2 15.9,2 16.135,1.765 19.331,1.765 19.866,2.3 20.219,2.3 20.804,1.715 22.784,1.715 22.969,1.9 25.231,1.9 25.531,1.6 28.383,1.6 28.658,1.875 29.005,1.875 29.38,1.5 29.6,1.5 29.7,1.6 v4(29.7,2) ; v3(20,24.9) v4(20.3,24.6)
  L10 w0.08: v4(12.2,5) 12.4,5 12.6,5.2 12.6,5.875 12.425,6.05 12.425,6.708 11.208,7.925 11.208,9.504 13.025,11.321 13.025,16.308 13.225,16.508 13.225,17.075 13.375,17.225 13.525,17.225 13.675,17.375 13.675,18.195 14.319,18.839 14.319,20.802 14.7,21.183 14.7,21.93 15.47,22.7 15.7,22.7 16.225,23.225 19.925,23.225 20.125,23.425 20.125,24.075 19.975,24.225 19.7,24.225 19.45,24.475 19.45,25.1 19.6,25.25 20.15,25.25 20.3,25.1 v4(20.3,24.6) ; v4(29.7,2) 29.75,1.95 v6(29.75,1.018)
  L11 w0.1: v5(29.75,0.617) v6(29.75,1.018)
  L12 w0.093: v5(29.75,0.617) J2.23@29.75,1.93
SD2_DATA2: J2.28 U1.A23 | length 56.9
  L1 w0.093: v2(16.4,28) U1.A23@16.9,28
  L2 w0.1: v2(16.4,28) v3(16.8,28)
  L3 w0.08: v4@8.3,12.4 8.43,12.4 8.975,11.855 8.975,10.625 8.825,10.475 8.375,10.475 8.125,10.225 8.125,8.175 8.375,7.925 8.625,7.925 8.925,8.225 9.175,8.225 9.475,7.925 9.725,7.925 9.875,8.075 9.875,8.275 10.1,8.5 10.77,8.5 12.395,10.125 14.375,10.125 15.675,8.825 15.675,8.412 16.062,8.025 16.825,8.025 17.1,8.3 18.494,8.3 19.444,7.35 21.866,7.35 22.766,6.45 25.969,6.45 26.369,6.05 27.348,6.05 27.78,5.618 v4(28.75,5.618) ; v2(16.4,28) v3(16.8,28)
  L10 w0.08: v4@8.3,12.4 8.3,12.413 9.4,13.513 9.4,14.77 9.7,15.07 9.7,15.4 9.375,15.725 9.375,18.975 10.375,19.975 10.375,24.491 10.6,24.716 10.6,25.383 13.067,27.85 13.4,27.85 13.55,27.7 13.55,27.475 13.7,27.325 13.95,27.325 14.1,27.475 14.1,28.3 14.25,28.45 14.6,28.45 14.75,28.3 14.75,28.075 14.9,27.925 15.15,27.925 15.3,28.075 15.3,28.3 15.45,28.45 15.7,28.45 16.15,28 v2(16.4,28) ; v4(28.75,5.618) v6(28.75,6.758)
  L11 w0.1: v5(28.75,6.358) v6(28.75,6.758)
  L12 w0.093: v5(28.75,6.358) J2.28@28.75,7.67
  other v4: 8.3,12.5 16.4,28
SD2_DATA3: J2.25 U1.B22 | length 56.9
  L1 w0.093: v2(17.3,27.6) U1.B22@17.7,27.2
  L2 w0.1: v2(17.3,27.6) v3(17.6,27.3)
  L3 w0.08: v4(13,3.9) 13,3.7 14.3,2.4 16.083,2.4 16.218,2.265 19.265,2.265 19.7,2.7 20.397,2.7 20.982,2.115 22.518,2.115 22.803,2.4 25.397,2.4 25.797,2 27.4,2 27.8,2.4 v4(28.9,2.4) ; v3(17.6,27.3) v4(18,27.3)
  L10 w0.08: v4(13,3.9) 12.885,4.015 12.885,5.985 12.675,6.195 12.675,6.791 11.425,8.041 11.425,9.438 13.225,11.238 13.225,16.225 13.42,16.42 13.7,16.42 13.975,16.695 13.975,17.005 13.9,17.08 13.9,18.137 14.519,18.756 14.519,20.598 15.525,21.604 15.525,22.055 16.47,23 19.983,23 20.208,23.225 20.655,23.225 20.9,23.47 20.9,24.587 21.375,25.062 21.375,25.725 19.875,27.225 19.475,27.225 19.3,27.4 19.3,27.8 19.1,28 17.9,28 17.7,27.8 17.7,27.6 v4(18,27.3) ; v4(28.9,2.4) 29.25,2.05 v6(29.25,1.017)
  L11 w0.1: v5(29.25,0.617) v6(29.25,1.017)
  L12 w0.093: v5(29.25,0.617) J2.25@29.25,1.93
SD2_DATA4: J2.30 U1.A19 | length 56.9
  L1 w0.093: U1.A19@16.9,24.8 v2(17.3,25.2)
  L2 w0.1: v3(16.9,25.2) v2(17.3,25.2)
  L3 w0.08: v4(9.5,12.8) 9,12.8 8.85,12.65 8.85,12.4 9,12.25 9.35,12.25 9.5,12.1 9.5,11.7 9.8,11.4 9.8,10.1 9.95,9.95 10.2,9.95 10.35,10.1 10.35,10.35 10.5,10.5 10.75,10.5 10.9,10.35 10.9,10.1 11.05,9.95 11.3,9.95 12,10.65 14.68,10.65 16.355,8.975 16.455,8.975 16.73,8.7 19.21,8.7 19.36,8.55 19.36,8.1 19.51,7.95 19.76,7.95 19.91,8.1 19.91,8.55 20.06,8.7 20.31,8.7 20.46,8.55 20.46,8.1 20.71,7.85 22.031,7.85 22.931,6.95 26.135,6.95 26.535,6.55 27.564,6.55 27.896,6.218 v4(28.25,6.218) ; v4(16.6,25.5) v3(16.9,25.2)
  L10 w0.08: v4(9.5,12.8) 9.5,11.77 9.745,11.525 10.055,11.525 10.3,11.77 10.3,12.5 10.125,12.675 10.125,14.646 10.3,14.821 10.3,15.7 10.125,15.875 10.125,18.726 11.125,19.726 11.125,24.055 11.35,24.28 11.35,24.9 11.5,25.05 11.75,25.05 11.9,24.9 11.9,23.9 12.05,23.75 12.3,23.75 12.45,23.9 12.45,25.725 12.6,25.875 12.85,25.875 13,25.725 13,24.925 13.15,24.775 13.4,24.775 13.55,24.925 13.55,25.3 13.7,25.45 13.95,25.45 14.1,25.3 14.1,24.925 14.25,24.775 14.5,24.775 14.65,24.925 14.65,25.047 15.178,25.575 16.525,25.575 v4(16.6,25.5) ; v4(28.25,6.218) v6(28.25,6.758)
  L11 w0.1: v5(28.25,6.358) v6(28.25,6.758)
  L12 w0.093: v5(28.25,6.358) J2.30@28.25,7.67
SD2_DATA5: J2.27 U1.B18 | length 57
  L1 w0.093: v2(17.3,24.4) U1.B18@17.7,24
  L2 w0.1: v3(17,24.1) v2(17.3,24.4)
  L3 w0.08: v4(11.5,5.6) 11.5,5.5 11.25,5.25 11.05,5.25 10.55,5.75 10.1,5.75 9.95,5.6 9.95,5.35 10.25,5.05 10.25,4.8 9.95,4.5 9.95,4.25 10.1,4.1 10.688,4.1 10.888,4.3 11.8,4.3 11.97,4.13 11.97,3.62 11.8,3.45 10.15,3.45 10,3.3 10,3.05 10.15,2.9 12.55,2.9 12.7,2.75 12.7,2.5 12.55,2.35 11.3,2.35 11.15,2.2 11.15,1.95 11.3,1.8 15.8,1.8 16.085,1.515 22.917,1.515 23.052,1.65 ; v4(16.6,24.1) v3(17,24.1) ; 23.084,1.65 25.148,1.65 25.398,1.4 28.75,1.4 v4(28.85,1.5)
  L10 w0.08: v4(11.5,5.6) 11.5,6.125 11.425,6.2 11.425,7.025 10.775,7.675 10.775,9.675 12.625,11.525 12.625,16.533 12.725,16.633 12.725,17.838 13.919,19.032 13.919,21.119 14.3,21.5 14.3,22.096 15.304,23.1 15.534,23.1 16.1,23.666 16.466,23.666 16.6,23.8 v4(16.6,24.1) ; v6(28.75,1.017) 28.75,1.4 v4(28.85,1.5)
  L11 w0.1: v5(28.75,0.617) v6(28.75,1.017)
  L12 w0.093: v5(28.75,0.617) J2.27@28.75,1.93
SD2_DATA6: J2.32 U1.E17 | length 56.9
  L1 w0.093: U1.E17@20.1,23.2 v2(20.5,22.8)
  L2 w0.1: v2(20.5,22.8) v3(20.8,23.1)
  L3 w0.08: v4(9.9,11.9) 10.2,11.6 10.2,11 10.35,10.85 10.6,10.85 10.75,11 10.75,11.35 10.9,11.5 11.15,11.5 11.3,11.35 11.3,11 11.45,10.85 11.7,10.85 11.85,11 11.85,11.35 12,11.5 12.25,11.5 12.4,11.35 12.4,11.1 12.575,10.925 14.788,10.925 16.813,8.9 18.5,8.9 18.6,9 20.293,9 21.193,8.1 22.114,8.1 23.014,7.2 26.218,7.2 26.618,6.8 27.352,6.8 v4(27.75,7.198) ; v4(20.5,23.6) 20.5,23.4 v3(20.8,23.1)
  L10 w0.08: v4(9.9,11.9) 9.9,14.704 10.1,14.904 10.1,15.566 9.875,15.791 9.875,18.809 10.875,19.809 10.875,24.225 11.1,24.45 11.1,25.1 12.825,26.825 16.689,26.825 16.82,26.955 16.82,27.725 16.945,27.85 17.195,27.85 17.32,27.725 17.32,26.955 17.45,26.825 18.395,26.825 18.575,27.005 18.575,27.475 18.725,27.625 18.975,27.625 19.1,27.5 19.1,26.6 19.275,26.425 20.275,26.425 21.175,25.525 21.175,25.145 20.675,24.645 20.675,24.4 20.5,24.225 v4(20.5,23.6) ; v6(27.75,6.758) v4(27.75,7.198) v4@27.75,7.298
  L11 w0.1: v5(27.75,6.358) v6(27.75,6.758)
  L12 w0.093: v5(27.75,6.358) J2.32@27.75,7.67
SD2_DATA7: J2.29 U1.C18 | length 56.9
  L1 w0.093: v4(18.1,23.6) U1.C18@18.5,24
  L2 w0.1: v4(18.1,23.6) v3(18.4,23.9)
  L3 w0.08: v4(11.2,3.9) 10,3.9 9.675,4.225 9.675,5.7 9.975,6 10.5,6 10.7,6.2 11.3,6.2 11.5,6 11.8,6 12.5,5.3 12.95,5.3 13.15,5.1 13.15,4.9 12.625,4.375 12.625,3.675 14.1,2.2 16,2.2 16.185,2.015 19.298,2.015 19.783,2.5 20.314,2.5 20.899,1.915 22.651,1.915 22.886,2.15 25.314,2.15 25.664,1.8 26,1.8 28.05,1.8 v4(28.25,2) ; v4(18.1,23.6) v3(18.4,23.9)
  L10 w0.08: v4(11.2,3.9) 12.2,3.9 12.35,4.05 12.35,4.3 12.2,4.45 11.575,4.45 11.325,4.7 11.325,4.895 12.175,5.745 12.175,6.558 10.992,7.741 10.992,9.571 12.825,11.404 12.825,16.45 12.925,16.55 12.925,17.755 14.119,18.949 14.119,20.885 14.5,21.266 14.5,22.013 15.387,22.9 15.617,22.9 16.142,23.425 16.595,23.425 17.145,23.975 17.455,23.975 17.83,23.6 v4(18.1,23.6) ; v6(28.25,1.018) v4(28.25,2)
  L11 w0.1: v5(28.25,0.617) v6(28.25,1.018)
  L12 w0.093: v5(28.25,0.617) J2.29@28.25,1.93
  other v2: 18.1,23.6
SD2_WP: J2.34 R43.1 U1.D17 | length 43
  L1 w0.093: U1.D17@19.3,23.2 v2(19.7,22.8)
  L2 w0.1: v3(19.4,23.1) v2(19.7,22.8)
  L3 w0.08: v4(11.8,8.8) 12.13,8.8 12.705,9.375 13.095,9.375 13.47,9 14.683,9 16.383,7.3 16.813,7.3 17.525,6.588 17.525,6.345 17.745,6.125 18.325,6.125 19.2,7 21.883,7 22.683,6.2 25.886,6.2 26.286,5.8 26.967,5.8 v4(27.25,5.518) ; v3(19.4,23.1) 19.4,22.9 v4(19.7,22.6)
  L10 w0.08: v5(11.8,8.9) v6(11.8,9.3) 12.025,9.525 12.025,9.755 12.67,10.4 13.3,10.4 13.975,11.075 13.975,13.075 14.1,13.2 14.1,14.617 13.975,14.742 13.975,16.412 14.2,16.637 14.2,17.287 14.125,17.362 14.125,17.979 14.819,18.673 14.819,20.615 15.704,21.5 16.03,21.5 16.275,21.745 16.275,22.375 16.7,22.8 19.5,22.8 v4(19.7,22.6) ; v4(27.25,5.518) v6(27.25,5.957)
  L11 w0.1: v5(11.8,8.9) v6(11.8,9.3) ; v6(27.25,5.957) v5(27.25,6.358)
  L12 w0.093: v5(11.8,8.9) 12.1,8.9 12.3,8.7 R43.1@12.3,8.3 ; v5(27.25,6.358) J2.34@27.25,7.67
SD3_CD: J1.34 R39.1 U1.A18 | length 48.6
  L1 w0.093: v2(16.5,23.6) U1.A18@16.9,24 ; v2(28.7,37.9) R39.1@28.7,38.5
  L2 w0.1: v3(16.1,23.6) v2(16.5,23.6) ; v3(28.3,37.9) v2(28.7,37.9)
  L3 w0.08: v4(6.2,31.8) 5.9,31.5 5.9,30.3 6.5,29.7 6.5,29.3 6.2,29 6.2,28 7.1,27.1 7.1,26.6 7.575,26.125 8.745,26.125 11.345,23.525 11.562,23.525 11.973,23.115 14.5,23.115 14.985,23.6 v3(16.1,23.6) ; v4(12.2,36.6) 12.87,36.6 13.545,35.925 14.055,35.925 15.125,36.995 15.125,37.255 15.345,37.475 15.942,37.475 16.592,36.825 17.134,36.825 17.384,36.575 18.78,36.575 19.301,37.096 20.266,37.096 20.47,37.3 23.661,37.3 24.261,37.9 24.6,37.9 25.085,38.385 25.9,38.385 26.342,37.943 v4(27.25,37.943) 28.258,37.943 v3(28.3,37.9)
  L10 w0.08: v4(6.2,31.8) 6.2,32.1 6.6,32.5 6.6,32.9 7.9,34.2 8.3,34.2 9.7,35.6 11.63,35.6 12.2,36.17 v4(12.2,36.6) ; v4(27.25,37.943) v6(27.25,38.982)
  L11 w0.1: v6(27.25,38.982) v5(27.25,39.383)
  L12 w0.093: J1.34@27.25,38.07 v5(27.25,39.383)
SD3_CLK: J1.27 R50.2 | length 45.6
  L1 w0.093: v2(11.2,21.6) 12,21.6 R50.2@12.4,21.2
  L2 w0.1: v3(10.8,21.6) v2(11.2,21.6)
  L3 w0.08: v4(4.9,26.1) 4.9,25.37 5.37,24.9 6.43,24.9 7.13,24.2 8.63,24.2 9.2,23.63 9.2,22.6 8.84,22.24 8.84,21.917 9.017,21.74 9.26,21.74 9.48,21.96 9.723,21.96 9.9,21.783 9.9,21.54 9.68,21.32 9.68,21.077 9.857,20.9 10.1,20.9 v3(10.8,21.6) ; v4(14.1,33.7) 14.275,33.525 15,33.525 15.125,33.4 17.5,33.4 18.4,32.5 19.07,32.5 19.345,32.225 19.855,32.225 20.08,32 23.8,32 23.95,32.15 25.45,32.15 25.9,31.7 27.892,31.7 v4(28.75,32.558)
  L10 w0.08: v4(4.9,26.1) 5.2,26.4 5.2,26.9 6.2,27.9 7.03,27.9 8.4,29.27 8.6,29.27 10.53,31.2 11.3,31.2 11.45,31.35 11.45,32 11.7,32.25 13.45,32.25 13.7,32.5 13.7,32.7 13.475,32.925 13.475,33.375 13.8,33.7 v4(14.1,33.7) ; v6(28.75,31.418) v4(28.75,32.558)
  L11 w0.1: v5(28.75,31.017) v6(28.75,31.418)
  L12 w0.093: v5(28.75,31.017) J1.27@28.75,32.33
SD3_CLK_R: R50.1 U1.D14 | length 8
  L1 w0.093: R50.1@12.4,20.2 v2(13,20.2) ; v2(18.9,20.4) U1.D14@19.3,20.8
  L2 w0.1: v2(13,20.2) v3(13,20.6) ; v3(18.6,20.7) v2(18.9,20.4)
  L3 w0.08: v3(13,20.6) 15.37,20.6 15.745,20.975 16.45,20.975 16.66,21.185 18.115,21.185 v3(18.6,20.7)
SD3_CMD: J1.33 R1.2 R38.1 | length 47.6
  L1 w0.093: v2(11.8,23.4) R1.2@12.4,23.4 ; v1(27.25,30.82) 28.72,30.82 29.1,31.2 R38.1@29.1,31.7
  L2 w0.1: v2(11.8,23.4) v3(12.2,23.4)
  L3 w0.08: v4(6.8,28.4) 6.8,28.2 7,28 7.3,28 7.55,27.75 7.55,26.75 7.7,26.6 7.95,26.6 8.1,26.75 8.1,27.25 8.25,27.4 8.5,27.4 8.65,27.25 8.65,26.55 8.8,26.4 9.23,26.4 9.455,26.175 9.755,26.175 9.975,25.955 9.975,25.74 10.415,25.3 10.415,25.085 11.225,24.275 11.655,24.275 11.9,24.03 11.9,23.7 v3(12.2,23.4) ; v4(13.2,33.7) 13.2,32.8 13.425,32.575 14.138,32.575 14.25,32.688 14.482,32.688 14.545,32.625 14.9,32.625 15.275,33 15.57,33 15.75,32.82 15.75,32.4 15.9,32.25 16.17,32.25 16.32,32.4 16.32,32.82 16.5,33 16.7,33 17.1,32.6 17.27,32.6 17.37,32.7 17.63,32.7 18.33,32 19.6,32 19.8,31.8 20.505,31.8 20.6,31.705 24.205,31.705 24.375,31.875 25.339,31.875 25.714,31.5 27,31.5 27.25,31.25 v1(27.25,30.82)
  L10 w0.08: v4(6.8,28.4) 6.7,28.3 6.5,28.3 6.35,28.45 6.35,28.7 6.5,28.85 6.9,28.85 7.088,29.038 7.088,29.262 6.95,29.4 6.95,29.65 7.1,29.8 8.2,29.8 8.35,29.95 8.35,30.2 8.2,30.35 7.95,30.35 7.8,30.5 7.8,30.75 7.95,30.9 8.3,30.9 8.575,31.175 9.475,31.175 9.625,31.325 9.625,31.575 9.475,31.725 9.305,31.725 9.155,31.875 9.155,32.125 9.305,32.275 10.025,32.275 10.2,32.1 10.2,31.8 10.35,31.65 10.6,31.65 10.75,31.8 10.75,32.75 10.9,32.9 11.1,32.9 11.4,32.6 12.8,32.6 13.2,33 v4(13.2,33.7)
  L12 w0.101: v1(27.25,30.82) J1.33@27.25,32.33
SD3_CMD_R: R1.1 U1.B13 | length 8.4
  L1 w0.093: v2(12.4,21.8) R1.1@12.4,22.4 ; v2(17.3,20.4) U1.B13@17.7,20
  L2 w0.1: v3(12.4,21.4) v2(12.4,21.8) ; v2@17.3,20.415 v3(17.6,20.115)
  L3 w0.08: v3(12.4,21.4) 12.4,20.425 12.7,20.125 15.5,20.125 15.6,20.225 16.945,20.225 17.055,20.115 v3(17.6,20.115)
SD3_DATA0: J1.29 U1.E14 | length 53.4
  L1 w0.093: v2(19.7,20.4) U1.E14@20.1,20.8
  L2 w0.1: v2(19.7,20.4) v3(20,20.7)
  L3 w0.08: v4(5,28.5) 5,27.785 5.275,27.51 5.275,27.062 6.837,25.5 7.67,25.5 8.245,24.925 9.026,24.925 10.125,23.826 10.125,23.375 10.925,22.575 11.664,22.575 11.889,22.35 12.733,22.35 12.908,22.175 15.292,22.175 15.902,22.785 17.3,22.785 17.67,22.415 18.215,22.415 18.475,22.155 18.475,21.895 18.795,21.575 19.055,21.575 19.275,21.355 19.275,21.095 19.67,20.7 v3(20,20.7) ; v4(12.8,35.1) 12.8,34.85 13.25,34.4 14.075,34.4 14.25,34.575 14.9,34.575 15.225,34.25 16.337,34.25 16.562,34.475 17.411,34.475 18.711,33.175 19.738,33.175 20.283,32.63 23.433,32.63 23.653,32.85 25.317,32.85 25.552,33.085 27.992,33.085 v4(28.25,33.343)
  L10 w0.08: v4(5,28.5) 5.5,29 5.5,29.63 5.8,29.93 5.8,30.45 7,31.65 7,31.8 7.362,32.162 7.362,32.793 7.945,33.375 9.275,33.375 9.7,33.8 9.7,34.4 10.175,34.875 10.555,34.875 11.205,34.225 12.355,34.225 12.8,34.67 v4(12.8,35.1) ; v4(28.25,33.343) v6(28.25,34.043)
  L11 w0.1: v5(28.25,33.643) v6(28.25,34.043)
  L12 w0.093: J1.29@28.25,32.33 v5(28.25,33.643)
SD3_DATA1: J1.30 U1.F14 | length 53.4
  L1 w0.093: v2(20.5,20.4) U1.F14@20.9,20.8
  L2 w0.1: v2(20.5,20.4) v3(20.8,20.7)
  L3 w0.08: v4(5.5,27.9) 5.5,27.17 6.97,25.7 8.534,25.7 10.325,23.909 10.325,23.7 11.225,22.8 11.722,22.8 11.922,22.6 12.783,22.6 12.9,22.483 15.217,22.483 15.719,22.985 17.645,22.985 17.93,22.7 19.003,22.7 20.125,21.578 20.125,21.045 20.47,20.7 v3(20.8,20.7) ; v4(13.7,36.3) 14.325,36.925 14.325,37.425 14.625,37.725 16.025,37.725 16.675,37.075 17.167,37.075 17.442,36.8 18.673,36.8 19.218,37.346 20.233,37.346 20.437,37.55 23.588,37.55 24.188,38.15 24.567,38.15 25.052,38.635 26.1,38.635 26.412,38.323 27.4,38.323 27.555,38.168 28.068,38.168 28.443,38.543 v4(28.55,38.543)
  L10 w0.08: v4(5.5,27.9) 5.5,28.57 6.4,29.47 6.4,30.2 8,31.8 8.3,31.8 9.3,32.8 9.6,32.8 10.4,33.6 12.5,33.6 13.4,34.5 13.4,36 v4(13.7,36.3) ; v6(28.25,38.982) 28.55,38.682 v4(28.55,38.543)
  L11 w0.1: v6(28.25,38.982) v5(28.25,39.383)
  L12 w0.093: J1.30@28.25,38.07 v5(28.25,39.383)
